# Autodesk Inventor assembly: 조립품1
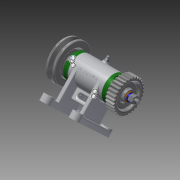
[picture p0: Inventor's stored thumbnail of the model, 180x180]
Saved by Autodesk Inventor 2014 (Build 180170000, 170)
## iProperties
Created: 2015-11
Part Number: 조립품1
Document SubType Name: Assembly
Designer: Owner
Author: Owner
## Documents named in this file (16)
- C:\Documents and Settings\Owner\바탕 화면\조립품1.iam
- C:\Documents and Settings\Owner\바탕 화면\부품1.ipt
- C:\Documents and Settings\Owner\바탕 화면\11.28\451109V1003\V벨트풀리.ipt
- C:\Documents and Settings\Owner\바탕 화면\11.28\451109V1003\키 3 x 3 x 12.ipt
- C:\Documents and Settings\Owner\바탕 화면\11.28\451109V1003\커버.ipt
- C:\Documents and Settings\Owner\바탕 화면\11.28\451109V1003\축.ipt
- C:\Documents and Settings\Owner\바탕 화면\11.28\451109V1003\와셔 8x17.ipt
- C:\Documents and Settings\Owner\바탕 화면\11.28\451109V1003\와셔 6x11.5.ipt
- C:\Documents and Settings\Owner\바탕 화면\11.28\451109V1003\오일 실 15 25 7.ipt
- C:\Documents and Settings\Owner\바탕 화면\11.28\451109V1003\스프링와셔 8.ipt
- C:\Documents and Settings\Owner\바탕 화면\11.28\451109V1003\스퍼기어.ipt
- C:\Documents and Settings\Owner\바탕 화면\11.28\451109V1003\볼트 M 6 x 8.ipt
- C:\Documents and Settings\Owner\바탕 화면\11.28\451109V1003\볼트 M4 x 12.ipt
- C:\Documents and Settings\Owner\바탕 화면\11.28\451109V1003\베어링 15 x 32 x 9.ipt
- C:\Documents and Settings\Owner\바탕 화면\11.28\451109V1003\니플 M 6 x 0.75.ipt
- C:\Documents and Settings\Owner\바탕 화면\11.28\451109V1003\너트 M 8.ipt
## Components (11 placed, 3 different names)
1. V벨트풀리:1 — 각도:3
2. KS B 2023 6002 - 15 x 32 x 9:1
3. KS B 2023 6002 - 15 x 32 x 9:2
4. ISO 4762 M4 x 12:1
5. ISO 4762 M4 x 12:2
6. ISO 4762 M4 x 12:3
7. ISO 4762 M4 x 12:4
8. ISO 4762 M4 x 12:5
9. ISO 4762 M4 x 12:6
10. ISO 4762 M4 x 12:7
11. ISO 4762 M4 x 12:8
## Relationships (1: Angle 1)
- 각도:3 [Angle]: V벨트풀리:1
